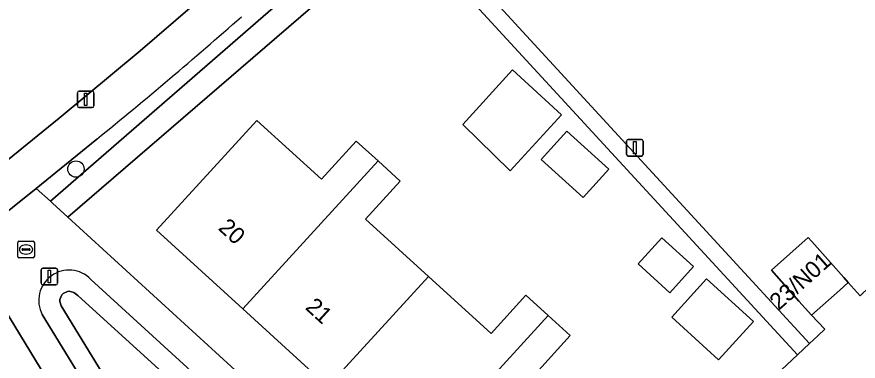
# Model space of a CAD drawing. Extents: x 162661 to 163484, y 380247 to 381230.
# Drawn here: x 163199.4 to 163250, y 381074.5 to 381095.2 of the extents above; entities that cross this region are included whole.
import ezdxf

# ---------------------------------------------------------------- set-up
doc = ezdxf.new("R2010")
doc.units = 0
for name, color, linetype in [('IMGEO_Boom', 7, 'Continuous'), ('IMGEO_Erf', 7, 'Continuous'), ('IMGEO_Groenvoorziening', 7, 'Continuous'), ('IMGEO_Hek', 7, 'Continuous'), ('IMGEO_Kolk', 7, 'Continuous'), ('IMGEO_Lichtmast', 7, 'Continuous'), ('IMGEO_Loofbos', 7, 'Continuous'), ('IMGEO_Pand', 7, 'Continuous'), ('IMGEO_Pand_nummerreeks', 7, 'Continuous'), ('IMGEO_Voetpad_open', 7, 'Continuous')]:
    doc.layers.add(name, color=color, linetype=linetype)

msp = doc.modelspace()

# ---------------------------------------------------------------- linework, layer by layer
at = {"layer": 'IMGEO_Boom'}
msp.add_circle((163202.957, 381086.015), 0.489, dxfattribs=at)
at = {"layer": 'IMGEO_Erf'}
for points in [[(163226.292, 381096.636), (163223.572, 381099.595), (163222.685, 381100.561), (163202.467, 381083.117), (163228.42, 381059.385), (163235.502, 381065.152)], [(163244.41, 381073.057), (163245.369, 381073.946), (163246.326, 381074.837), (163226.292, 381096.636)], [(163183.983, 381058.045), (163198.909, 381037.268), (163207.172, 381043.323), (163215.696, 381049.583), (163215.608, 381049.723), (163210.472, 381058.155), (163197.39, 381079.623), (163187.607, 381072.029), (163175.603, 381063.541), (163168.423, 381058.662), (163158.593, 381052.674), (163180.067, 381024.856)]]:
    msp.add_lwpolyline(points, dxfattribs=at)
for points in [[(163226.204, 381088.703), (163229.196, 381091.98), (163232.15, 381089.282), (163229.066, 381085.904)], [(163224.14, 381079.559), (163227.912, 381076.127), (163230.002, 381078.425), (163231.349, 381077.2), (163232.662, 381076.005), (163230.571, 381073.705), (163234.457, 381070.168), (163228.393, 381063.536), (163223.199, 381068.276), (163218.093, 381072.937), (163212.985, 381077.599), (163207.789, 381082.341), (163213.829, 381088.944), (163217.716, 381085.407), (163219.799, 381087.697), (163221.114, 381086.5), (163222.451, 381085.283), (163220.367, 381082.992)], [(163230.915, 381086.594), (163232.466, 381088.3), (163234.987, 381086.008), (163233.436, 381084.302)], [(163236.741, 381080.314), (163238.168, 381081.884), (163240.08, 381080.146), (163238.652, 381078.576)], [(163238.768, 381077.103), (163240.86, 381079.404), (163243.674, 381076.846), (163241.582, 381074.544)]]:
    msp.add_lwpolyline(points, close=True, dxfattribs=at)
at = {"layer": 'IMGEO_Groenvoorziening'}
for points in [[(163221.736, 381110.562), (163205.378, 381127.154), (163185.077, 381111.602), (163188.453, 381107.232), (163185.916, 381104.822), (163181.838, 381101.796), (163194.064, 381089.109), (163197.533, 381085.509), (163201.94, 381089.082), (163206.811, 381093.132), (163212.113, 381097.704)], [(163204.217, 381087.82), (163200.571, 381084.851), (163201.418, 381084.076), (163221.659, 381101.677)], [(163218.225, 381066.231), (163203.86, 381079.379)], [(163200.931, 381077.264), (163210.856, 381061.018)]]:
    msp.add_lwpolyline(points, dxfattribs=at)
for points in [[(163222.685, 381100.561), (163221.659, 381101.677), (163201.418, 381084.076), (163201.546, 381083.959), (163202.467, 381083.117)], [(163212.357, 381061.455), (163212.752, 381061.459), (163213.263, 381061.681), (163217.011, 381065.716), (163203.062, 381078.415), (163202.836, 381078.585), (163202.553, 381078.666), (163202.445, 381078.657), (163202.18, 381078.528), (163202.106, 381078.449), (163201.996, 381078.175), (163201.993, 381078.043), (163202.075, 381077.791), (163211.825, 381061.83), (163212.17, 381061.525)], [(163202.075, 381077.791), (163201.993, 381078.043), (163201.996, 381078.175), (163202.106, 381078.449), (163202.18, 381078.528), (163202.445, 381078.657), (163202.553, 381078.666), (163202.836, 381078.585), (163203.062, 381078.415), (163217.011, 381065.716), (163213.263, 381061.681), (163212.752, 381061.459), (163212.357, 381061.455), (163212.17, 381061.525), (163211.825, 381061.83)]]:
    msp.add_lwpolyline(points, close=True, dxfattribs=at)
for centre, radius, start, end in [((163030.934, 381301.257), 274.922, 309.07223, 311.44308), ((163202.547, 381078.111), 1.825, 43.9961, 207.6693)]:
    msp.add_arc(centre, radius, start, end, dxfattribs=at)
at = {"layer": 'IMGEO_Hek'}
msp.add_lwpolyline([(163226.292, 381096.636), (163246.326, 381074.837)], dxfattribs=at)
at = {"layer": 'IMGEO_Kolk'}
for p, q in [((163199.455, 381080.75), (163199.455, 381081.602)), ((163199.53, 381081.676), (163200.382, 381081.676)), ((163200.456, 381081.602), (163200.456, 381080.75)), ((163199.714, 381081.17), (163199.714, 381081.182)), ((163200.152, 381081.133), (163199.754, 381081.133)), ((163199.757, 381081.219), (163200.155, 381081.219)), ((163199.943, 381081.456), (163199.968, 381081.456)), ((163200.198, 381081.182), (163200.198, 381081.17)), ((163200.382, 381080.676), (163199.53, 381080.676)), ((163199.966, 381080.896), (163199.941, 381080.896))]:
    msp.add_line(p, q, dxfattribs=at)
for points in [[(163199.455, 381080.75), (163199.455, 381081.602)], [(163199.53, 381081.676), (163200.382, 381081.676)], [(163200.456, 381081.602), (163200.456, 381080.75)], [(163200.382, 381080.676), (163199.53, 381080.676)]]:
    msp.add_lwpolyline(points, dxfattribs=at)
for centre, radius, start, end in [((163199.532, 381081.6), 0.0765, 91.552, 178.448), ((163199.532, 381081.6), 0.0765, 91.552, 178.448), ((163200.38, 381081.6), 0.0765, 1.552, 88.448), ((163200.38, 381081.6), 0.0765, 1.552, 88.448), ((163199.754, 381081.179), 0.0403, 85.8775, 175.7526), ((163199.751, 381081.169), 0.0366, 178.938, 274.7102), ((163200.155, 381081.176), 0.043, 264.8664, 352.4533), ((163200.159, 381081.181), 0.0386, 1.7309, 96.639), ((163199.532, 381080.752), 0.0765, 181.552, 268.448), ((163199.532, 381080.752), 0.0765, 181.552, 268.448), ((163200.38, 381080.752), 0.0765, 271.552, 358.448), ((163200.38, 381080.752), 0.0765, 271.552, 358.448)]:
    msp.add_arc(centre, radius, start, end, dxfattribs=at)
for centre, major_axis, ratio, start_param, end_param in [((163199.942, 381081.176), (-0.387, 0.002), 0.722429, 4.712389, 7.853982), ((163199.967, 381081.176), (-0.39, 0.002), 0.717154, 1.570796, 4.712389)]:
    msp.add_ellipse(centre, major_axis=major_axis, ratio=ratio, start_param=start_param, end_param=end_param, dxfattribs=at)
at = {"layer": 'IMGEO_Lichtmast'}
for p, q in [((163203.044, 381089.807), (163203.044, 381090.607)), ((163203.044, 381090.607), (163203.044, 381089.807)), ((163203.144, 381090.707), (163203.934, 381090.707)), ((163203.934, 381090.707), (163203.144, 381090.707)), ((163204.034, 381090.607), (163204.034, 381089.807)), ((163204.034, 381089.807), (163204.034, 381090.607)), ((163203.934, 381089.707), (163203.144, 381089.707)), ((163203.144, 381089.707), (163203.934, 381089.707)), ((163236.053, 381086.899), (163236.053, 381087.699)), ((163236.053, 381087.699), (163236.053, 381086.899)), ((163236.153, 381087.799), (163236.943, 381087.799)), ((163236.943, 381087.799), (163236.153, 381087.799)), ((163237.043, 381087.699), (163237.043, 381086.899)), ((163237.043, 381086.899), (163237.043, 381087.699)), ((163236.943, 381086.799), (163236.153, 381086.799)), ((163236.153, 381086.799), (163236.943, 381086.799)), ((163200.958, 381080.048), (163201.748, 381080.048)), ((163201.748, 381080.048), (163200.958, 381080.048)), ((163200.858, 381079.148), (163200.858, 381079.948)), ((163200.858, 381079.948), (163200.858, 381079.148)), ((163201.848, 381079.948), (163201.848, 381079.148)), ((163201.848, 381079.148), (163201.848, 381079.948)), ((163201.748, 381079.048), (163200.958, 381079.048)), ((163200.958, 381079.048), (163201.748, 381079.048))]:
    msp.add_line(p, q, dxfattribs=at)
for points in [[(163203.464, 381090.582), (163203.614, 381090.582), (163203.614, 381089.832), (163203.464, 381089.832), (163203.464, 381090.582)], [(163236.473, 381087.674), (163236.623, 381087.674), (163236.623, 381086.924), (163236.473, 381086.924), (163236.473, 381087.674)], [(163201.278, 381079.923), (163201.428, 381079.923), (163201.428, 381079.173), (163201.278, 381079.173), (163201.278, 381079.923)]]:
    msp.add_lwpolyline(points, dxfattribs=at)
for centre, start, end in [((163203.144, 381090.607), 90, 180), ((163203.144, 381090.607), 90, 180), ((163203.934, 381090.607), 0, 90), ((163203.934, 381090.607), 360, 90), ((163203.144, 381089.807), 180, 270), ((163203.144, 381089.807), 180, 270), ((163203.934, 381089.807), 270, 0), ((163203.934, 381089.807), 270, 0), ((163236.153, 381087.699), 90, 180), ((163236.153, 381087.699), 90, 180), ((163236.943, 381087.699), 0, 90), ((163236.943, 381087.699), 360, 90), ((163236.153, 381086.899), 180, 270), ((163236.153, 381086.899), 180, 270), ((163236.943, 381086.899), 270, 0), ((163236.943, 381086.899), 270, 0), ((163200.958, 381079.948), 90, 180), ((163200.958, 381079.948), 90, 180), ((163201.748, 381079.948), 0, 90), ((163201.748, 381079.948), 360, 90), ((163200.958, 381079.148), 180, 270), ((163200.958, 381079.148), 180, 270), ((163201.748, 381079.148), 270, 0), ((163201.748, 381079.148), 270, 0)]:
    msp.add_arc(centre, 0.1, start, end, dxfattribs=at)
at = {"layer": 'IMGEO_Loofbos'}
msp.add_lwpolyline([(163222.168, 381103.519), (163223.903, 381101.612), (163223.452, 381101.222), (163227.048, 381097.305), (163247.049, 381075.519), (163247.567, 381076.005), (163247.961, 381076.375), (163247.166, 381077.219), (163246.408, 381078.073), (163244.76, 381079.929), (163246.97, 381081.891), (163247.181, 381081.654), (163249.108, 381079.483), (163249.376, 381079.181), (163250.091, 381078.391), (163252.905, 381081.1)], dxfattribs=at)
at = {"layer": 'IMGEO_Pand'}
for points in [[(163226.204, 381088.703), (163229.066, 381085.904), (163232.15, 381089.282), (163229.196, 381091.98)], [(163212.985, 381077.599), (163221.114, 381086.5), (163219.799, 381087.697), (163217.716, 381085.407), (163213.829, 381088.944), (163207.789, 381082.341)], [(163230.915, 381086.594), (163233.436, 381084.302), (163234.987, 381086.008), (163232.466, 381088.3)], [(163212.985, 381077.599), (163218.093, 381072.937), (163224.14, 381079.559), (163220.367, 381082.992), (163222.451, 381085.283), (163221.114, 381086.5)], [(163236.741, 381080.314), (163238.652, 381078.576), (163240.08, 381080.146), (163238.168, 381081.884)], [(163247.181, 381081.654), (163246.97, 381081.891), (163244.76, 381079.929), (163246.408, 381078.073), (163247.166, 381077.219), (163248.871, 381078.733), (163249.376, 381079.181), (163249.108, 381079.483)], [(163224.14, 381079.559), (163218.093, 381072.937), (163223.199, 381068.276), (163231.349, 381077.2), (163230.002, 381078.425), (163227.912, 381076.127)], [(163238.768, 381077.103), (163241.582, 381074.544), (163243.674, 381076.846), (163240.86, 381079.404)], [(163223.199, 381068.276), (163228.393, 381063.536), (163234.457, 381070.168), (163230.571, 381073.705), (163232.662, 381076.005), (163231.349, 381077.2)]]:
    msp.add_lwpolyline(points, close=True, dxfattribs=at)
at = {"layer": 'IMGEO_Voetpad_open'}
for points in [[(163212.113, 381097.704), (163206.811, 381093.132), (163201.94, 381089.082), (163197.533, 381085.509), (163196.141, 381084.403), (163192.481, 381081.536), (163187.377, 381077.705), (163182.692, 381074.309), (163172.038, 381066.893)], [(163196.28, 381081.408), (163200.571, 381084.851), (163204.217, 381087.82)], [(163203.86, 381079.379), (163218.225, 381066.231), (163218.707, 381065.79), (163218.639, 381065.715), (163225.974, 381059.047), (163228.42, 381059.385), (163202.467, 381083.117), (163201.546, 381083.959), (163201.418, 381084.076), (163200.571, 381084.851), (163196.28, 381081.408), (163196.99, 381080.281), (163197.39, 381079.623), (163210.472, 381058.155), (163213.82, 381060.479)], [(163252.905, 381081.1), (163250.091, 381078.391), (163249.376, 381079.181), (163248.871, 381078.733), (163247.166, 381077.219), (163247.961, 381076.375), (163247.567, 381076.005), (163247.049, 381075.519), (163246.326, 381074.837), (163245.369, 381073.946), (163244.41, 381073.057)], [(163210.856, 381061.018), (163200.931, 381077.264)]]:
    msp.add_lwpolyline(points, dxfattribs=at)
msp.add_lwpolyline([(163247.049, 381075.519), (163227.048, 381097.305), (163226.292, 381096.636), (163246.326, 381074.837)], close=True, dxfattribs=at)
for centre, radius, start, end in [((163030.934, 381301.257), 274.922, 309.07223, 311.44308), ((163202.547, 381078.111), 1.825, 43.9961, 207.6693)]:
    msp.add_arc(centre, radius, start, end, dxfattribs=at)

# ---------------------------------------------------------------- texts
at = {"layer": 'IMGEO_Pand_nummerreeks'}
for s, rotation, p in [('20', 317.6137, (163211.455, 381082.406)), ('23/N01', 41.6025, (163245.202, 381077.482)), ('21', 317.6137, (163216.687, 381077.631))]:
    msp.add_text(s, height=1, rotation=rotation, dxfattribs=at).set_placement(p)

doc.saveas('drawing.dxf')
